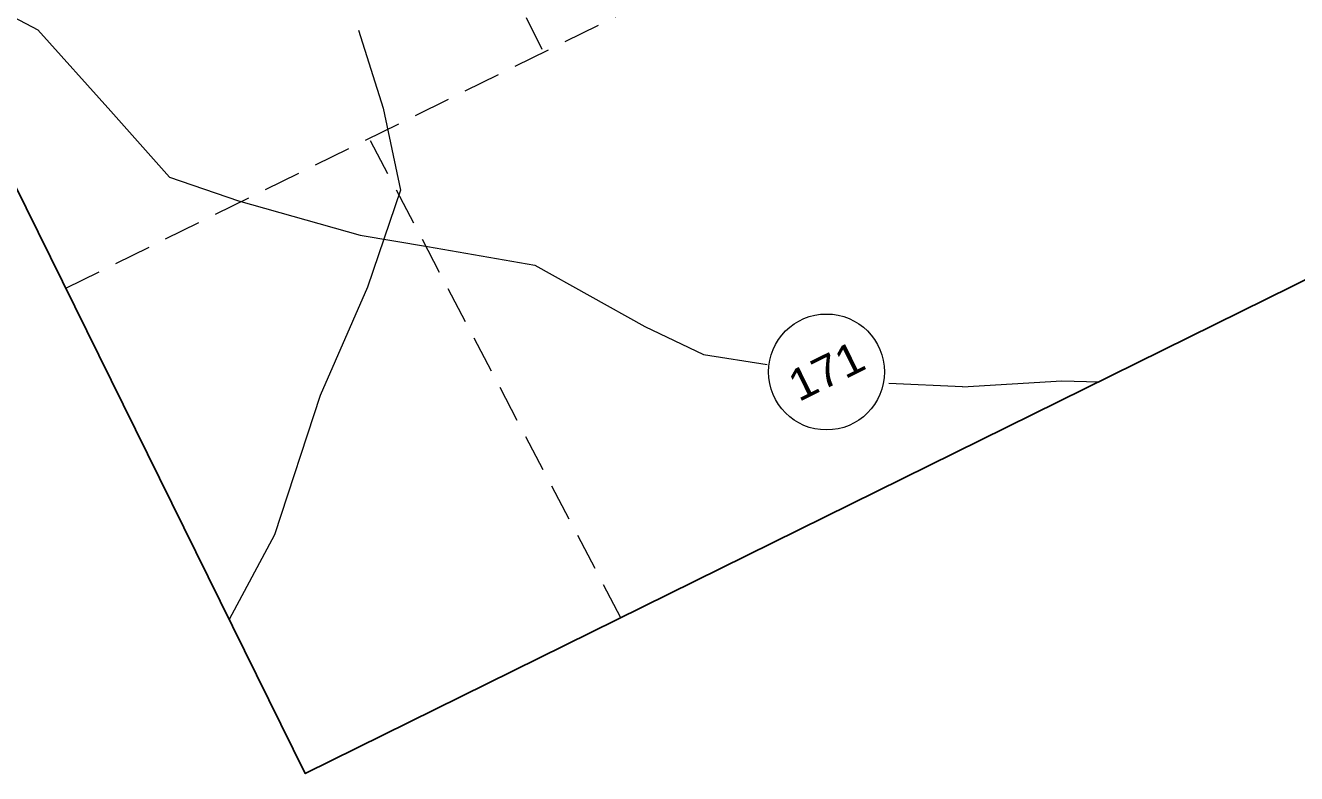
# Model space of a CAD drawing. Extents: x 2356606 to 2371222, y 6973096 to 6982644.
# Drawn here: x 2370773.7 to 2370979.1, y 6980110.7 to 6980231.5 of the extents above; entities that cross this region are included whole.
import ezdxf

# ---------------------------------------------------------------- set-up
doc = ezdxf.new("R2010")
doc.units = 0
doc.header["$LTSCALE"] = 2
doc.linetypes.add('MEDIUM_DASHED', pattern=[4.5, 3, -1.5])
doc.layers.add('62', color=7, linetype='Continuous', lineweight=13)
doc.layers.add('63', color=7, linetype='Continuous', lineweight=13)

msp = doc.modelspace()

# ---------------------------------------------------------------- linework, layer by layer
at = {"layer": '62', "linetype": 'MEDIUM_DASHED'}
for p, q in [((2370774.944, 6980394.196), (2370857.153, 6980227.678)), ((2370780.217, 6980189.078), (2371183.383, 6980388.055)), ((2370869.928, 6980135.841), (2370829.133, 6980213.521))]:
    msp.add_line(p, q, dxfattribs=at)
at = {"layer": '62'}
for p, q in [((2370873.785, 6980182.887), (2370883.251, 6980178.35)), ((2370883.251, 6980178.35), (2370893.567, 6980176.767)), ((2370925.128, 6980173.12), (2370913.25, 6980173.705))]:
    msp.add_line(p, q, dxfattribs=at)
at = {"layer": '62', "lineweight": 25}
msp.add_lwpolyline([(2370613.001, 6980527.892), (2370818.917, 6980110.665), (2371222.081, 6980309.64), (2371016.165, 6980726.869)], dxfattribs=at)
at = {"layer": '62'}
for points in [[(2370754.237, 6980241.723), (2370759.679, 6980239.289), (2370775.687, 6980230.804), (2370787.493, 6980217.661), (2370796.976, 6980207.036), (2370808.115, 6980203.175), (2370827.813, 6980197.635), (2370838.663, 6980195.838), (2370856.034, 6980192.821), (2370873.785, 6980182.887)], [(2370827.501, 6980230.755), (2370831.512, 6980218.159), (2370834.33, 6980204.919), (2370828.996, 6980189.237), (2370821.307, 6980171.719), (2370813.956, 6980149.245), (2370806.628, 6980135.565)], [(2370925.128, 6980173.12), (2370941.175, 6980174.115), (2370947.172, 6980173.962)]]:
    msp.add_lwpolyline(points, dxfattribs=at)
msp.add_circle((2370903.16, 6980175.543), 9.364, dxfattribs=at)
at = {"layer": '63', "linetype": 'MEDIUM_DASHED'}
for p, q in [((2370774.944, 6980394.196), (2370857.153, 6980227.678)), ((2370780.217, 6980189.078), (2371183.383, 6980388.055)), ((2370869.928, 6980135.841), (2370829.133, 6980213.521))]:
    msp.add_line(p, q, dxfattribs=at)
at = {"layer": '63'}
for p, q in [((2370873.785, 6980182.887), (2370883.251, 6980178.35)), ((2370883.251, 6980178.35), (2370893.567, 6980176.767)), ((2370925.128, 6980173.12), (2370913.25, 6980173.705))]:
    msp.add_line(p, q, dxfattribs=at)
at = {"layer": '63', "lineweight": 25}
msp.add_lwpolyline([(2370613.001, 6980527.892), (2370818.917, 6980110.665), (2371222.081, 6980309.64), (2371016.165, 6980726.869)], dxfattribs=at)
at = {"layer": '63'}
for points in [[(2370754.237, 6980241.723), (2370759.679, 6980239.289), (2370775.687, 6980230.804), (2370787.493, 6980217.661), (2370796.976, 6980207.036), (2370808.115, 6980203.175), (2370827.813, 6980197.635), (2370838.663, 6980195.838), (2370856.034, 6980192.821), (2370873.785, 6980182.887)], [(2370827.501, 6980230.755), (2370831.512, 6980218.159), (2370834.33, 6980204.919), (2370828.996, 6980189.237), (2370821.307, 6980171.719), (2370813.956, 6980149.245), (2370806.628, 6980135.565)], [(2370925.128, 6980173.12), (2370941.175, 6980174.115), (2370947.172, 6980173.962)]]:
    msp.add_lwpolyline(points, dxfattribs=at)
msp.add_circle((2370903.16, 6980175.543), 9.364, dxfattribs=at)

# ---------------------------------------------------------------- texts
at = {"layer": '62', "width": 1.1}
msp.add_text('171', height=5.099, rotation=26.268, dxfattribs=at).set_placement((2370898.648, 6980170.644))
at = {"layer": '63', "width": 1.1}
msp.add_text('171', height=5.099, rotation=26.268, dxfattribs=at).set_placement((2370898.648, 6980170.644))

doc.saveas('drawing.dxf')
